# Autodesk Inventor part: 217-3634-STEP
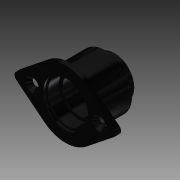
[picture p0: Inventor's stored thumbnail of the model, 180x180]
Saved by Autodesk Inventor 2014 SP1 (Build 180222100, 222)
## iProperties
Created: 2014-06
Part Number: 217-3634-STEP
Material: Aluminum 6061
Document SubType Name: Modeling
Designer: Michael
Density: 2.71 g/cm^3
Appearance: Glossy - Black
Author: Michael
Title: 217-3634-STEP.STEP
Description: STEP AP214
Creation Date: 2013-12-10
Sending System: SolidWorks 2013
Preprocessor: SwSTEP 2.0
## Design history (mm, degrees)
node "217-3634-STEP1"
node "Chamfer1"
node "Base1"
